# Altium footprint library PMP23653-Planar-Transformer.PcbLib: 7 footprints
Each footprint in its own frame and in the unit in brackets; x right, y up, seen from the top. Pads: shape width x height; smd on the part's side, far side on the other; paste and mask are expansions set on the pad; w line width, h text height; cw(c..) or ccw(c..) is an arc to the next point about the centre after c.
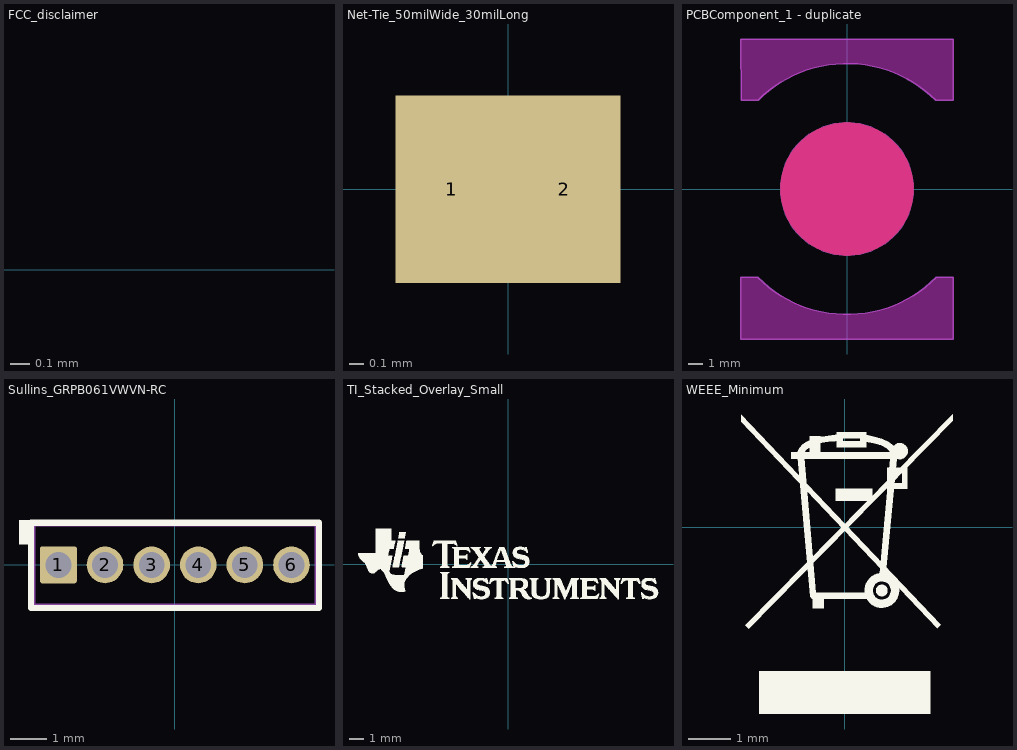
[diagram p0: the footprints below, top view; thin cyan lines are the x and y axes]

## CE_Mark_5mm [mm] "Minimum text height for CE Mark"
height 0.7

## FCC_disclaimer [mm]
height 0.7
Top Overlay:
  text "For evaluation only; not FCC approved for resale." at -15.928,-0.353 h1.52

## Net-Tie_50milWide_30milLong [mil] "50mil net tie, no solder mask opening, no solder paste"
height 27.56
pads (2):
  rect 30x50 smd paste-20 mask-20: 1(-15,0) 2(15,0)

## PCBComponent_1 - duplicate [mm]
Top Layer:
  pour cut-out: 0,-4.6 -0.302,-4.6 -0.899,-4.521 -1.482,-4.365 -2.039,-4.134 -2.561,-3.833 -3.04,-3.466 -3.466,-3.04 -3.833,-2.561 -4.134,-2.039 -4.365,-1.482 -4.521,-0.899 -4.6,-0.302 -4.6,0 -4.6,0.301 -4.521,0.899 -4.365,1.482 -4.134,2.039 -3.833,2.561 -3.466,3.039 -3.04,3.466 -2.561,3.833 -2.039,4.134 -1.482,4.365 -0.899,4.521 -0.302,4.6 0,4.6 0.301,4.6 0.899,4.521 1.482,4.365 2.039,4.134 2.561,3.833 3.039,3.466 3.466,3.039 3.833,2.561 4.134,2.039 4.365,1.482 4.521,0.899 4.6,0.301 4.6,0 4.6,-0.302 4.521,-0.899 4.365,-1.482 4.134,-2.039 3.833,-2.561 3.466,-3.04 3.039,-3.466 2.561,-3.833 2.039,-4.134 1.482,-4.365 0.899,-4.521 0.301,-4.6
Keep-Out Layer:
  board cut-out: 0,-4.6 -0.302,-4.6 -0.899,-4.521 -1.482,-4.365 -2.039,-4.134 -2.561,-3.833 -3.04,-3.466 -3.466,-3.04 -3.833,-2.561 -4.134,-2.039 -4.365,-1.482 -4.521,-0.899 -4.6,-0.302 -4.6,0 -4.6,0.301 -4.521,0.899 -4.365,1.482 -4.134,2.039 -3.833,2.561 -3.466,3.039 -3.04,3.466 -2.561,3.833 -2.039,4.134 -1.482,4.365 -0.899,4.521 -0.302,4.6 0,4.6 0.301,4.6 0.899,4.521 1.482,4.365 2.039,4.134 2.561,3.833 3.039,3.466 3.466,3.039 3.833,2.561 4.134,2.039 4.365,1.482 4.521,0.899 4.6,0.301 4.6,0 4.6,-0.302 4.521,-0.899 4.365,-1.482 4.134,-2.039 3.833,-2.561 3.466,-3.04 3.039,-3.466 2.561,-3.833 2.039,-4.134 1.482,-4.365 0.899,-4.521 0.301,-4.6
  board cut-out: -7.35,-10.4 -7.35,-6.127 -6.176,-6.127 -5.867,-6.424 -5.205,-6.971 -4.493,-7.45 -3.737,-7.856 -2.945,-8.186 -2.125,-8.437 -1.283,-8.605 -0.429,-8.689 0.429,-8.689 1.283,-8.605 2.125,-8.437 2.945,-8.186 3.737,-7.856 4.493,-7.45 5.205,-6.971 5.867,-6.424 6.176,-6.127 7.35,-6.127 7.35,-10.4
  board cut-out: -7.348,6.152 -6.164,6.14 -5.855,6.435 -5.195,6.979 -4.485,7.455 -3.732,7.859 -2.943,8.187 -2.125,8.437 -1.287,8.604 -0.436,8.689 0.419,8.69 1.27,8.607 2.108,8.441 2.926,8.193 3.716,7.866 4.47,7.464 5.181,6.989 5.842,6.447 6.152,6.152 7.35,6.152 7.35,10.4 -7.35,10.4
Mechanical 1:
  circle w0.1: c0,0 r4.6
  lines w0.1: -7.35,-10.4 -7.35,-6.127 -6.176,-6.127 ccw(c0,0) 6.176,-6.127 7.35,-6.127 7.35,-10.4 -7.35,-10.4 ; -7.35,10.4 7.35,10.4 7.35,6.152 6.152,6.152 ccw(c0,0) -6.164,6.14 -7.348,6.152 -7.35,10.4
Mechanical 5:
  text ".Designator" at -1.8,-0.514 h1.02

## Sullins_GRPB061VWVN-RC [mm] "SULLINS"
height 4
pads (6):
  rrect10% 1x1 hole 0.7: 1(-3.175,0)
  round 1 hole 0.7: 2(-1.905,0) 3(-0.635,0) 4(0.635,0) 5(1.905,0) 6(3.175,0)
Top Overlay:
  rectangle: -4.25,0.55 -3.925,1.225
  lines w0.17: -3.925,-1.175 -3.925,0.125 -3.925,1.15 3.925,1.15 3.925,0.825 3.925,-0.25 3.925,-1.175 -3.925,-1.175
Mechanical 5:
  lines w0.1: -3.85,-1.1 -3.85,1.1 3.85,1.1 3.85,-1.1 -3.85,-1.1
  text ".Designator" at -1.9,-0.5 h1.02
3D body: height 4.3, standoff -2.3, extent 2.975,-0.2 3.375,0.2
3D body: height 4.3, standoff -2.3, extent 1.705,-0.2 2.105,0.2
3D body: height 4.3, standoff -2.3, extent 0.435,-0.2 0.835,0.2
3D body: height 4.3, standoff -2.3, extent -2.105,-0.2 -1.705,0.2
3D body: height 4.3, standoff -2.3, extent -3.375,-0.2 -2.975,0.2
3D body: height 4.3, standoff -2.3, extent -0.835,-0.2 -0.435,0.2
3D body: height 1, standoff 0, extent -3.849,-1.099 3.849,1.099

## TI_Stacked_Overlay_Small [mm]
height 0.7
Top Overlay:
  drawing of 18 lines, arcs and shapes, not listed

## WEEE_Minimum [mm] "WEEElie bin"
height 0.7
Top Overlay:
  drawing of 23 lines, arcs and shapes, not listed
